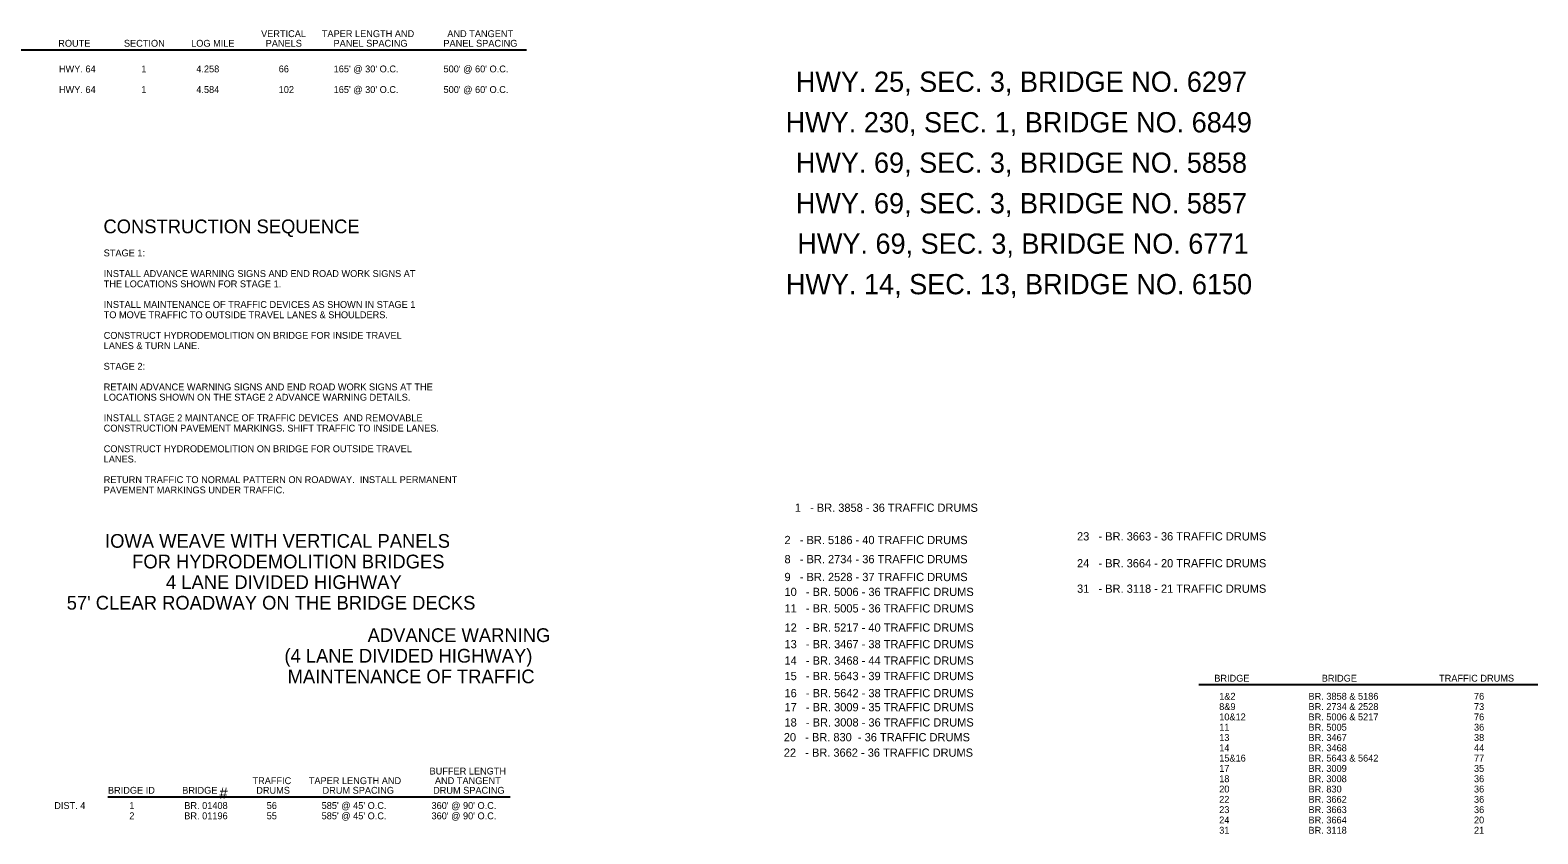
# Model space of a CAD drawing. Extents: x 1930579 to 1937521, y 596183 to 597599.
# Drawn here: x 1936204 to 1937521, y 596183 to 596885 of the extents above; entities that cross this region are included whole.
import ezdxf

# ---------------------------------------------------------------- set-up
doc = ezdxf.new("R2010")
doc.units = 0
doc.layers.add('Default', color=7, linetype='Continuous')
doc.layers.add('R_Annotation', color=7, linetype='Continuous')

msp = doc.modelspace()

# ---------------------------------------------------------------- linework, layer by layer
at = {"layer": 'R_Annotation'}
for p, q in [((1936090.3, 596867.8), (1936637.5, 596867.8)), ((1937224.8, 596313.5), (1937521.1, 596313.5)), ((1936271.8, 596215.4), (1936623.1, 596215.4))]:
    msp.add_line(p, q, dxfattribs=at)

# ---------------------------------------------------------------- texts
at = {"layer": 'Default'}
for s, p in [('HWY. 25, SEC. 3, BRIDGE NO. 6297', (1936872.8, 596831.1)), ('HWY. 230, SEC. 1, BRIDGE NO. 6849', (1936863.9, 596795.7)), ('HWY. 69, SEC. 3, BRIDGE NO. 5858', (1936872.8, 596760.4)), ('HWY. 69, SEC. 3, BRIDGE NO. 5857', (1936872.8, 596725)), ('HWY. 69, SEC. 3, BRIDGE NO. 6771', (1936874.1, 596689.7)), ('HWY. 14, SEC. 13, BRIDGE NO. 6150', (1936864.1, 596654.3))]:
    msp.add_text(s, height=17.682, rotation=360, dxfattribs=at).set_placement(p)
for s, p in [('IOWA WEAVE WITH VERTICAL PANELS', (1936269.3, 596432.9)), ('FOR HYDRODEMOLITION BRIDGES', (1936293, 596414.9)), ('4 LANE DIVIDED HIGHWAY', (1936322.5, 596396.9)), ("57' CLEAR ROADWAY ON THE BRIDGE DECKS", (1936235.8, 596378.9))]:
    msp.add_text(s, height=12, dxfattribs=at).set_placement(p)
at = {"layer": 'R_Annotation'}
for s, height, p in [('VERTICAL', 6, (1936405.6, 596878.9)), ('TAPER LENGTH AND', 6, (1936458.7, 596878.9)), ('AND TANGENT', 6, (1936568.3, 596878.9)), ('ROUTE', 6, (1936228.4, 596870.5)), ('SECTION', 6, (1936285.8, 596870.5)), ('LOG MILE', 6, (1936344.5, 596870.5)), ('PANELS', 6, (1936409.6, 596870.5)), ('PANEL SPACING', 6, (1936468.9, 596870.5)), ('PANEL SPACING', 6, (1936564.9, 596870.5)), ('HWY. 64', 6, (1936229, 596848.1)), ('1', 6, (1936301, 596848.1)), ('4.258', 6, (1936349, 596848.1)), ('66', 6, (1936421, 596848.1)), ("165' @ 30' O.C.", 6, (1936469, 596848.1)), ("500' @ 60' O.C.", 6, (1936565, 596848.1)), ('HWY. 64', 6, (1936229, 596830.1)), ('1', 6, (1936301, 596830.1)), ('4.584', 6, (1936349, 596830.1)), ('102', 6, (1936421, 596830.1)), ("165' @ 30' O.C.", 6, (1936469, 596830.1)), ("500' @ 60' O.C.", 6, (1936565, 596830.1)), ('CONSTRUCTION SEQUENCE', 12, (1936267.9, 596707.6)), ('STAGE 1:', 6, (1936268.1, 596687.4)), ('INSTALL ADVANCE WARNING SIGNS AND END ROAD WORK SIGNS AT', 6, (1936268.1, 596669.4)), ('THE LOCATIONS SHOWN FOR STAGE 1.', 6, (1936268.1, 596660.4)), ('INSTALL MAINTENANCE OF TRAFFIC DEVICES AS SHOWN IN STAGE 1', 6, (1936268.1, 596642.4)), ('TO MOVE TRAFFIC TO OUTSIDE TRAVEL LANES & SHOULDERS.', 6, (1936268.1, 596633.4)), ('CONSTRUCT HYDRODEMOLITION ON BRIDGE FOR INSIDE TRAVEL', 6, (1936268.1, 596615.4)), ('LANES & TURN LANE.', 6, (1936268.1, 596606.4)), ('STAGE 2:', 6, (1936268.1, 596588.4)), ('RETAIN ADVANCE WARNING SIGNS AND END ROAD WORK SIGNS AT THE', 6, (1936268.1, 596570.4)), ('LOCATIONS SHOWN ON THE STAGE 2 ADVANCE WARNING DETAILS.', 6, (1936268.1, 596561.4)), ('INSTALL STAGE 2 MAINTANCE OF TRAFFIC DEVICES  AND REMOVABLE', 6, (1936268.1, 596543.4)), ('CONSTRUCTION PAVEMENT MARKINGS. SHIFT TRAFFIC TO INSIDE LANES.', 6, (1936268.1, 596534.4)), ('CONSTRUCT HYDRODEMOLITION ON BRIDGE FOR OUTSIDE TRAVEL', 6, (1936268.1, 596516.4)), ('LANES.', 6, (1936268.1, 596507.4)), ('RETURN TRAFFIC TO NORMAL PATTERN ON ROADWAY.  INSTALL PERMANENT', 6, (1936268.1, 596489.4)), ('PAVEMENT MARKINGS UNDER TRAFFIC.', 6, (1936268.1, 596480.4)), ('1   - BR. 3858 - 36 TRAFFIC DRUMS', 7.2, (1936871.9, 596464.3)), ('2   - BR. 5186 - 40 TRAFFIC DRUMS', 7.2, (1936862.9, 596436.1)), ('23   - BR. 3663 - 36 TRAFFIC DRUMS', 7.2, (1937118.5, 596439.3)), ('8   - BR. 2734 - 36 TRAFFIC DRUMS', 7.2, (1936862.9, 596419.4)), ('24   - BR. 3664 - 20 TRAFFIC DRUMS', 7.2, (1937118.5, 596415.8)), ('9   - BR. 2528 - 37 TRAFFIC DRUMS', 7.2, (1936862.9, 596403.8)), ('10   - BR. 5006 - 36 TRAFFIC DRUMS', 7.2, (1936862.9, 596390.8)), ('31   - BR. 3118 - 21 TRAFFIC DRUMS', 7.2, (1937118.5, 596393.6)), ('11   - BR. 5005 - 36 TRAFFIC DRUMS', 7.2, (1936862.9, 596376.4)), ('ADVANCE WARNING ', 12, (1936498.7, 596350.6)), ('12   - BR. 5217 - 40 TRAFFIC DRUMS', 7.2, (1936862.9, 596359.6)), ('(4 LANE DIVIDED HIGHWAY)', 12, (1936426, 596332.6)), ('13   - BR. 3467 - 38 TRAFFIC DRUMS', 7.2, (1936862.9, 596345.2)), ('14   - BR. 3468 - 44 TRAFFIC DRUMS', 7.2, (1936862.9, 596330.8)), ('MAINTENANCE OF TRAFFIC', 12, (1936428.8, 596314.6)), ('15   - BR. 5643 - 39 TRAFFIC DRUMS', 7.2, (1936862.9, 596317.3)), ('BRIDGE ', 6, (1937238.4, 596316)), ('BRIDGE ', 6, (1937332.3, 596316)), ('TRAFFIC DRUMS', 6, (1937434.8, 596316)), ('16   - BR. 5642 - 38 TRAFFIC DRUMS', 7.2, (1936862.9, 596302.4)), ('1&2', 6, (1937242.7, 596300.2)), ('BR. 3858 & 5186', 6, (1937320.7, 596300.2)), ('76', 6, (1937465.3, 596300.2)), ('17   - BR. 3009 - 35 TRAFFIC DRUMS', 7.2, (1936862.9, 596290.1)), ('8&9', 6, (1937242.7, 596291.2)), ('BR. 2734 & 2528', 6, (1937320.7, 596291.2)), ('73', 6, (1937465.3, 596291.2)), ('18   - BR. 3008 - 36 TRAFFIC DRUMS', 7.2, (1936862.9, 596276.8)), ('10&12', 6, (1937242.7, 596282.2)), ('11', 6, (1937242.7, 596273.2)), ('BR. 5006 & 5217', 6, (1937320.7, 596282.2)), ('BR. 5005', 6, (1937320.7, 596273.2)), ('36', 6, (1937465.3, 596273.2)), ('76', 6, (1937465.3, 596282.2)), ('20   - BR. 830  - 36 TRAFFIC DRUMS', 7.2, (1936862.3, 596263.9)), ('13', 6, (1937242.7, 596264.2)), ('BR. 3467', 6, (1937320.7, 596264.2)), ('38', 6, (1937465.3, 596264.2)), ('22   - BR. 3662 - 36 TRAFFIC DRUMS', 7.2, (1936862.3, 596250.4)), ('14', 6, (1937242.7, 596255.2)), ('15&16', 6, (1937242.7, 596246.2)), ('BR. 3468', 6, (1937320.7, 596255.2)), ('BR. 5643 & 5642', 6, (1937320.7, 596246.2)), ('44', 6, (1937465.3, 596255.2)), ('77', 6, (1937465.3, 596246.2)), ('BUFFER LENGTH', 6, (1936552.8, 596234.9)), ('17', 6, (1937242.7, 596237.2)), ('BR. 3009', 6, (1937320.7, 596237.2)), ('35', 6, (1937465.3, 596237.2)), ('TRAFFIC', 6, (1936398.1, 596226.5)), ('TAPER LENGTH AND', 6, (1936447.3, 596226.5)), ('AND TANGENT', 6, (1936557.5, 596226.5)), ('20', 6, (1937242.7, 596219.2)), ('18', 6, (1937242.7, 596228.2)), ('BR. 3008', 6, (1937320.7, 596228.2)), ('BR. 830', 6, (1937320.7, 596219.2)), ('36', 6, (1937465.3, 596228.2)), ('36', 6, (1937465.3, 596219.2)), ('BRIDGE ID', 6, (1936271.8, 596218.1)), ('BRIDGE ', 6, (1936336.7, 596218.1)), ('#', 9.6, (1936369.2, 596213.9)), ('DRUMS', 6, (1936401.4, 596218.1)), ('DRUM SPACING', 6, (1936459.3, 596218.1)), ('DRUM SPACING', 6, (1936555.9, 596218.1)), ('22', 6, (1937242.7, 596210.2)), ('BR. 3662', 6, (1937320.7, 596210.2)), ('36', 6, (1937465.3, 596210.2)), ('DIST. 4', 6, (1936224.9, 596204.8)), ('2', 6, (1936290.5, 596195.8)), ('1', 6, (1936290.5, 596204.8)), ('BR. 01408', 6, (1936338.5, 596204.8)), ('BR. 01196', 6, (1936338.5, 596195.8)), ('56', 6, (1936410.5, 596204.8)), ('55', 6, (1936410.5, 596195.8)), ("585' @ 45' O.C.", 6, (1936458.5, 596204.8)), ("585' @ 45' O.C.", 6, (1936458.5, 596195.8)), ("360' @ 90' O.C.", 6, (1936554.5, 596204.8)), ("360' @ 90' O.C.", 6, (1936554.5, 596195.8)), ('23', 6, (1937242.7, 596201.2)), ('24', 6, (1937242.7, 596192.2)), ('BR. 3663', 6, (1937320.7, 596201.2)), ('BR. 3664', 6, (1937320.7, 596192.2)), ('36', 6, (1937465.3, 596201.2)), ('20', 6, (1937465.3, 596192.2)), ('31', 6, (1937242.7, 596183.2)), ('BR. 3118', 6, (1937320.7, 596183.2)), ('21', 6, (1937465.3, 596183.2))]:
    msp.add_text(s, height=height, rotation=360, dxfattribs=at).set_placement(p)

doc.saveas('drawing.dxf')
